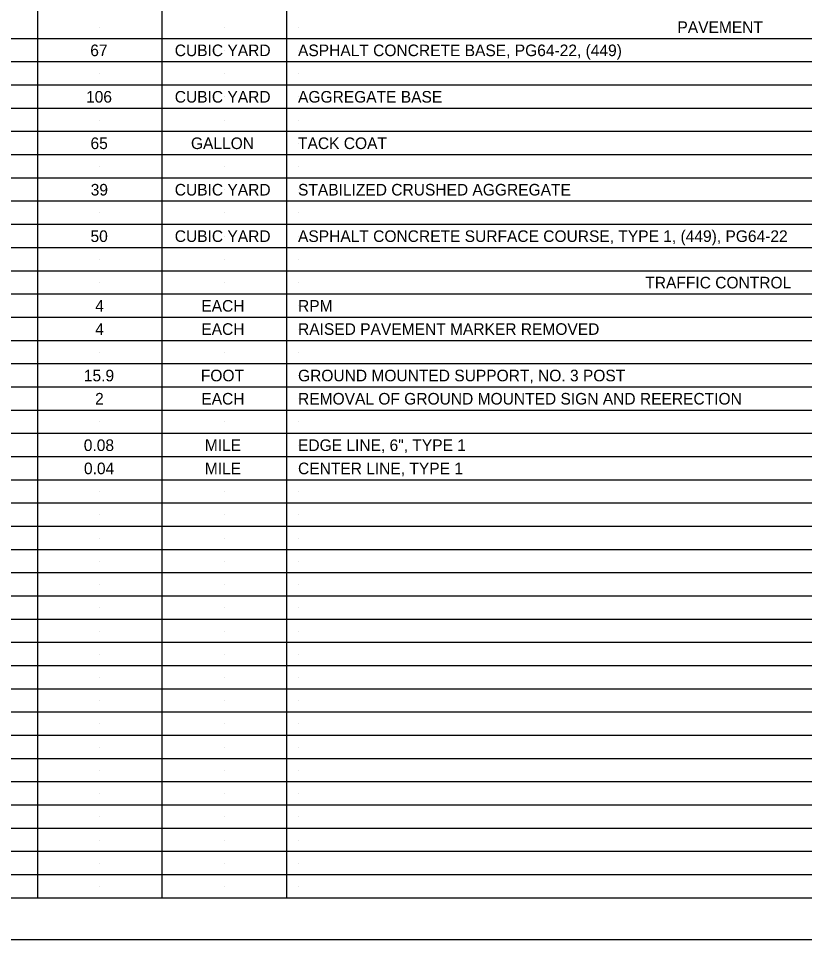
# Model space of a CAD drawing. Extents: x 0 to 34, y 0 to 22.
# Drawn here: x 17.27 to 26.74, y 0 to 11.1 of the extents above; entities that cross this region are included whole.
import ezdxf

# ---------------------------------------------------------------- set-up
doc = ezdxf.new("R2010")
doc.units = 0
for name, color, linetype in [('RD_P_Text', 7, 'Continuous'), ('SC_Scratch1', 7, 'Continuous'), ('SH_Border', 7, 'Continuous'), ('SH_Cut_Line', 7, 'Continuous'), ('SH_Data', 7, 'Continuous')]:
    doc.layers.add(name, color=color, linetype=linetype)

msp = doc.modelspace()

# ---------------------------------------------------------------- linework, layer by layer
at = {"layer": 'SC_Scratch1'}
for p, q in [((18.25, 11), (18.25, 11)), ((19.75, 11), (19.75, 11)), ((20.64, 11), (20.64, 11)), ((18.25, 10.72), (18.25, 10.72)), ((19.75, 10.72), (19.75, 10.72)), ((20.64, 10.72), (20.64, 10.72)), ((18.25, 10.44), (18.25, 10.44)), ((19.75, 10.44), (19.75, 10.44)), ((20.64, 10.44), (20.64, 10.44)), ((18.25, 10.16), (18.25, 10.16)), ((19.75, 10.16), (19.75, 10.16)), ((20.64, 10.16), (20.64, 10.16)), ((18.25, 9.88), (18.25, 9.88)), ((19.75, 9.88), (19.75, 9.88)), ((20.64, 9.88), (20.64, 9.88)), ((18.25, 9.6), (18.25, 9.6)), ((19.75, 9.6), (19.75, 9.6)), ((20.64, 9.6), (20.64, 9.6)), ((18.25, 9.32), (18.25, 9.32)), ((19.75, 9.32), (19.75, 9.32)), ((20.64, 9.32), (20.64, 9.32)), ((18.25, 9.04), (18.25, 9.04)), ((19.75, 9.04), (19.75, 9.04)), ((20.64, 9.04), (20.64, 9.04)), ((18.25, 8.76), (18.25, 8.76)), ((19.75, 8.76), (19.75, 8.76)), ((20.64, 8.76), (20.64, 8.76)), ((18.25, 8.48), (18.25, 8.48)), ((19.75, 8.48), (19.75, 8.48)), ((20.64, 8.48), (20.64, 8.48)), ((18.25, 8.2), (18.25, 8.2)), ((19.75, 8.2), (19.75, 8.2)), ((20.64, 8.2), (20.64, 8.2)), ((18.25, 7.92), (18.25, 7.92)), ((19.75, 7.92), (19.75, 7.92)), ((20.64, 7.92), (20.64, 7.92)), ((18.25, 7.64), (18.25, 7.64)), ((19.75, 7.64), (19.75, 7.64)), ((20.64, 7.64), (20.64, 7.64)), ((18.25, 7.36), (18.25, 7.36)), ((19.75, 7.36), (19.75, 7.36)), ((20.64, 7.36), (20.64, 7.36)), ((18.25, 7.08), (18.25, 7.08)), ((19.75, 7.08), (19.75, 7.08)), ((20.64, 7.08), (20.64, 7.08)), ((18.25, 6.8), (18.25, 6.8)), ((19.75, 6.8), (19.75, 6.8)), ((20.64, 6.8), (20.64, 6.8)), ((18.25, 6.52), (18.25, 6.52)), ((19.75, 6.52), (19.75, 6.52)), ((20.64, 6.52), (20.64, 6.52)), ((18.25, 6.24), (18.25, 6.24)), ((19.75, 6.24), (19.75, 6.24)), ((20.64, 6.24), (20.64, 6.24)), ((18.25, 5.96), (18.25, 5.96)), ((19.75, 5.96), (19.75, 5.96)), ((20.64, 5.96), (20.64, 5.96)), ((18.25, 5.68), (18.25, 5.68)), ((19.75, 5.68), (19.75, 5.68)), ((20.64, 5.68), (20.64, 5.68)), ((18.25, 5.4), (18.25, 5.4)), ((19.75, 5.4), (19.75, 5.4)), ((20.64, 5.4), (20.64, 5.4)), ((18.25, 5.12), (18.25, 5.12)), ((19.75, 5.12), (19.75, 5.12)), ((20.64, 5.12), (20.64, 5.12)), ((18.25, 4.84), (18.25, 4.84)), ((19.75, 4.84), (19.75, 4.84)), ((20.64, 4.84), (20.64, 4.84)), ((18.25, 4.56), (18.25, 4.56)), ((19.75, 4.56), (19.75, 4.56)), ((20.64, 4.56), (20.64, 4.56)), ((18.25, 4.28), (18.25, 4.28)), ((19.75, 4.28), (19.75, 4.28)), ((20.64, 4.28), (20.64, 4.28)), ((18.25, 4), (18.25, 4)), ((19.75, 4), (19.75, 4)), ((20.64, 4), (20.64, 4)), ((18.25, 3.72), (18.25, 3.72)), ((19.75, 3.72), (19.75, 3.72)), ((20.64, 3.72), (20.64, 3.72)), ((18.25, 3.44), (18.25, 3.44)), ((19.75, 3.44), (19.75, 3.44)), ((20.64, 3.44), (20.64, 3.44)), ((18.25, 3.16), (18.25, 3.16)), ((19.75, 3.16), (19.75, 3.16)), ((20.64, 3.16), (20.64, 3.16)), ((18.25, 2.88), (18.25, 2.88)), ((19.75, 2.88), (19.75, 2.88)), ((20.64, 2.88), (20.64, 2.88)), ((18.25, 2.6), (18.25, 2.6)), ((19.75, 2.6), (19.75, 2.6)), ((20.64, 2.6), (20.64, 2.6)), ((18.25, 2.32), (18.25, 2.32)), ((19.75, 2.32), (19.75, 2.32)), ((20.64, 2.32), (20.64, 2.32)), ((18.25, 2.04), (18.25, 2.04)), ((19.75, 2.04), (19.75, 2.04)), ((20.64, 2.04), (20.64, 2.04)), ((18.25, 1.76), (18.25, 1.76)), ((19.75, 1.76), (19.75, 1.76)), ((20.64, 1.76), (20.64, 1.76)), ((18.25, 1.48), (18.25, 1.48)), ((19.75, 1.48), (19.75, 1.48)), ((20.64, 1.48), (20.64, 1.48)), ((18.25, 1.2), (18.25, 1.2)), ((19.75, 1.2), (19.75, 1.2)), ((20.64, 1.2), (20.64, 1.2)), ((18.25, 0.92), (18.25, 0.92)), ((19.75, 0.92), (19.75, 0.92)), ((20.64, 0.92), (20.64, 0.92)), ((18.25, 0.64), (18.25, 0.64)), ((19.75, 0.64), (19.75, 0.64)), ((20.64, 0.64), (20.64, 0.64))]:
    msp.add_line(p, q, dxfattribs=at)
at = {"layer": 'SH_Border'}
msp.add_lwpolyline([(1.5, 21.5), (33.5, 21.5), (33.5, 0.5), (1.5, 0.5)], close=True, dxfattribs=at)
at = {"layer": 'SH_Cut_Line'}
msp.add_lwpolyline([(0, 0), (34, 0), (34, 22), (0, 22)], close=True, dxfattribs=at)
at = {"layer": 'SH_Data'}
for p, q in [((17.5, 21.5), (17.5, 0.5)), ((19, 21.5), (19, 0.5)), ((20.5, 21.5), (20.5, 0.5)), ((32, 10.86), (1.5, 10.86)), ((32, 10.58), (1.5, 10.58)), ((32, 10.3), (1.5, 10.3)), ((32, 10.02), (1.5, 10.02)), ((32, 9.74), (1.5, 9.74)), ((32, 9.46), (1.5, 9.46)), ((32, 9.18), (1.5, 9.18)), ((32, 8.9), (1.5, 8.9)), ((32, 8.62), (1.5, 8.62)), ((32, 8.34), (1.5, 8.34)), ((32, 8.06), (1.5, 8.06)), ((32, 7.78), (1.5, 7.78)), ((32, 7.5), (1.5, 7.5)), ((32, 7.22), (1.5, 7.22)), ((32, 6.94), (1.5, 6.94)), ((32, 6.66), (1.5, 6.66)), ((32, 6.38), (1.5, 6.38)), ((32, 6.1), (1.5, 6.1)), ((32, 5.82), (1.5, 5.82)), ((32, 5.54), (1.5, 5.54)), ((32, 5.26), (1.5, 5.26)), ((32, 4.98), (1.5, 4.98)), ((32, 4.7), (1.5, 4.7)), ((32, 4.42), (1.5, 4.42)), ((32, 4.14), (1.5, 4.14)), ((32, 3.86), (1.5, 3.86)), ((32, 3.58), (1.5, 3.58)), ((32, 3.3), (1.5, 3.3)), ((32, 3.02), (1.5, 3.02)), ((32, 2.74), (1.5, 2.74)), ((32, 2.46), (1.5, 2.46)), ((32, 2.18), (1.5, 2.18)), ((32, 1.9), (1.5, 1.9)), ((32, 1.62), (1.5, 1.62)), ((32, 1.34), (1.5, 1.34)), ((32, 1.06), (1.5, 1.06)), ((32, 0.78), (1.5, 0.78))]:
    msp.add_line(p, q, dxfattribs=at)

# ---------------------------------------------------------------- texts
at = {"layer": 'RD_P_Text'}
for s, p in [('PAVEMENT', (25.211, 10.93)), ('67', (18.137, 10.65)), ('CUBIC YARD', (19.155, 10.65)), ('ASPHALT CONCRETE BASE, PG64-22, (449)', (20.64, 10.65)), ('106', (18.086, 10.09)), ('CUBIC YARD', (19.155, 10.09)), ('AGGREGATE BASE', (20.64, 10.09)), ('65', (18.14, 9.53)), ('GALLON', (19.35, 9.53)), ('TACK COAT', (20.64, 9.53)), ('39', (18.142, 8.97)), ('CUBIC YARD', (19.155, 8.97)), ('STABILIZED CRUSHED AGGREGATE', (20.64, 8.97)), ('50', (18.14, 8.41)), ('CUBIC YARD', (19.155, 8.41)), ('ASPHALT CONCRETE SURFACE COURSE, TYPE 1, (449), PG64-22', (20.64, 8.41)), ('TRAFFIC CONTROL', (24.824, 7.85)), ('4', (18.197, 7.57)), ('EACH', (19.475, 7.57)), ('RPM', (20.64, 7.57)), ('4', (18.197, 7.29)), ('EACH', (19.475, 7.29)), ('RAISED PAVEMENT MARKER REMOVED', (20.64, 7.29)), ('15.9', (18.06, 6.73)), ('FOOT', (19.469, 6.73)), ('GROUND MOUNTED SUPPORT, NO. 3 POST', (20.64, 6.73)), ('2', (18.195, 6.45)), ('EACH', (19.475, 6.45)), ('REMOVAL OF GROUND MOUNTED SIGN AND REERECTION', (20.64, 6.45)), ('0.08', (18.059, 5.89)), ('MILE', (19.517, 5.89)), ('EDGE LINE, 6", TYPE 1', (20.64, 5.89)), ('0.04', (18.061, 5.61)), ('MILE', (19.517, 5.61)), ('CENTER LINE, TYPE 1', (20.64, 5.61))]:
    msp.add_text(s, height=0.14, dxfattribs=at).set_placement(p)

doc.saveas('drawing.dxf')
